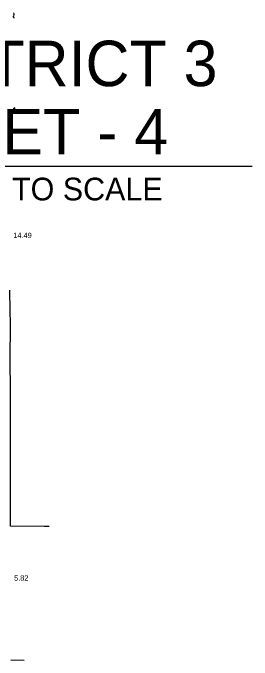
# Model space of a CAD drawing. Extents: x 31699 to 244310, y -8841 to 11474.
# Drawn here: x 94063 to 95322, y -7347 to -3933 of the extents above; entities that cross this region are included whole.
import ezdxf

# ---------------------------------------------------------------- set-up
doc = ezdxf.new("R2010")
doc.units = 0
for name, color, linetype in [('Level 48', 7, 'Continuous'), ('R_Draft', 7, 'Continuous'), ('R_Logo', 7, 'Continuous'), ('S_WALL_ANNOT', 7, 'Continuous')]:
    doc.layers.add(name, color=color, linetype=linetype)

msp = doc.modelspace()

# ---------------------------------------------------------------- linework, layer by layer
at = {"layer": 'Level 48'}
msp.add_line((93322.3, -4740.7), (95322.3, -4740.7), dxfattribs=at)
at = {"layer": 'R_Draft'}
for points in [[(94069.7, -3960), (94068.3, -3958.5), (94067.7, -3957.6), (94066.6, -3955.8), (94066.2, -3954.8), (94065.7, -3952.6), (94065.6, -3950.3), (94066.8, -3948.5), (94068.1, -3947.4), (94069.4, -3946.8), (94069.5, -3946.8)], [(94069.3, -3936.8), (94068.5, -3936.7), (94067.4, -3936.3), (94066.7, -3935.1), (94067.1, -3934.2), (94067.4, -3933.7), (94068.5, -3933.2), (94069.2, -3933.1)], [(94069.3, -3942.4), (94069.1, -3941.5), (94069.1, -3939.7), (94069.3, -3938.9)], [(94069.4, -3942.5), (94069.3, -3942.4)], [(94078.6, -4442.8), (94078.5, -4442.8), (94076, -4443.7), (94074.6, -4444.3), (94072.8, -4443.1), (94072.5, -4441), (94072.4, -4438.2), (94072.6, -4436.6), (94071.8, -4434.7), (94070.5, -4434.3), (94068.1, -4435.7), (94067.2, -4437.3), (94066.2, -4439.4), (94065.1, -4441.3), (94065.2, -4442.4), (94065, -4444.4), (94063.3, -4444.7), (94060.8, -4444.8)]]:
    msp.add_lwpolyline(points, dxfattribs=at)
at = {"layer": 'R_Logo'}
for points in [[(94252.8, -6642.6), (94227.9, -6642.5), (94049.5, -6641), (94050.3, -6464.6), (94049.5, -6285.2), (94049.3, -6108.6), (94049.1, -5932.9), (94047.1, -5755.3), (94048.9, -5581), (94045.9, -5405.3), (94045.7, -5395.1)], [(94050.8, -7344.6), (94121.4, -7346.6)]]:
    msp.add_lwpolyline(points, dxfattribs=at)

# ---------------------------------------------------------------- texts
at = {"layer": 'Level 48'}
for s, height, p in [('DISTRICT 3', 240, (93392.8, -4319.4)), ('INSET - 4', 240, (93472.2, -4679.4)), ('NOT TO SCALE', 120, (93674.4, -4922))]:
    msp.add_text(s, height=height, dxfattribs=at).set_placement(p)
at = {"layer": 'S_WALL_ANNOT'}
for s, p in [('14.49', (94064.4, -5120.5)), ('5.82', (94068.5, -6927.7))]:
    msp.add_text(s, height=28.16, dxfattribs=at).set_placement(p)

doc.saveas('drawing.dxf')
